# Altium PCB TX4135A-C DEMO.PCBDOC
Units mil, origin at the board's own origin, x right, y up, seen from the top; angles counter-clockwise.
Board outline 1900 x 1181.1 mil, 2 copper layers (Top Layer, Bottom Layer); 15 components, 16 nets, 45 pads, 125 vias.
Unrouted connection lines stored in the file: 6.
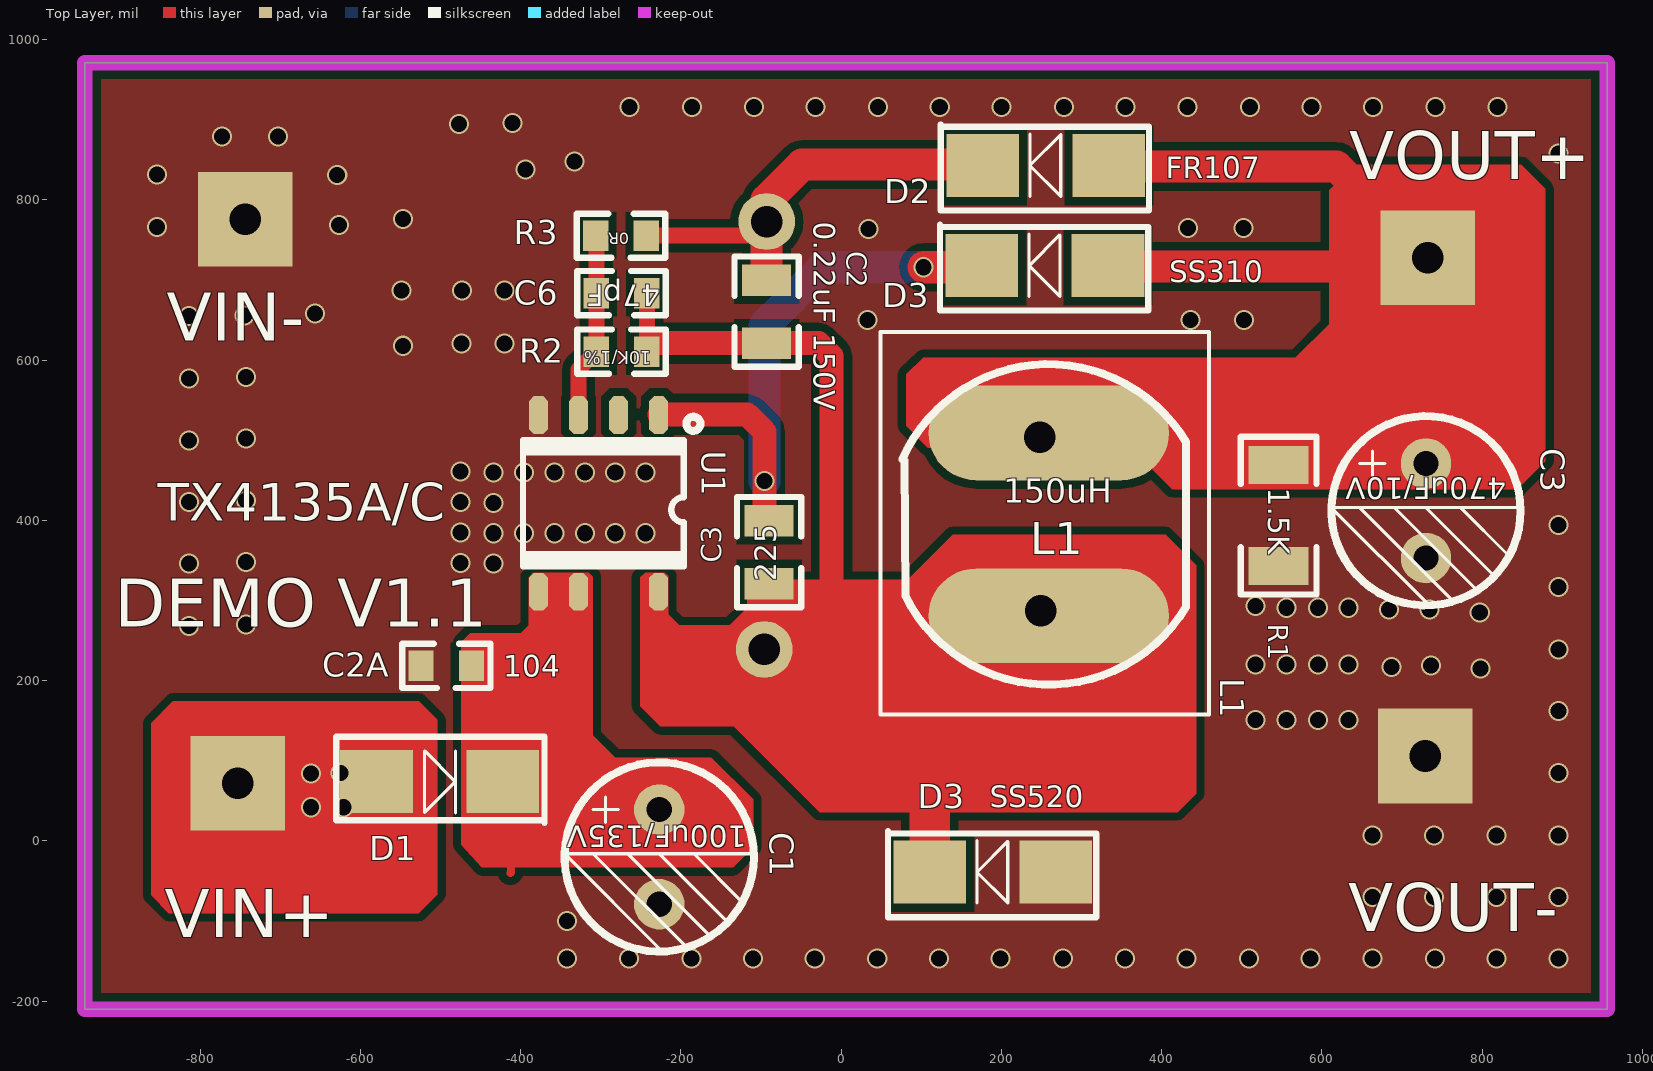
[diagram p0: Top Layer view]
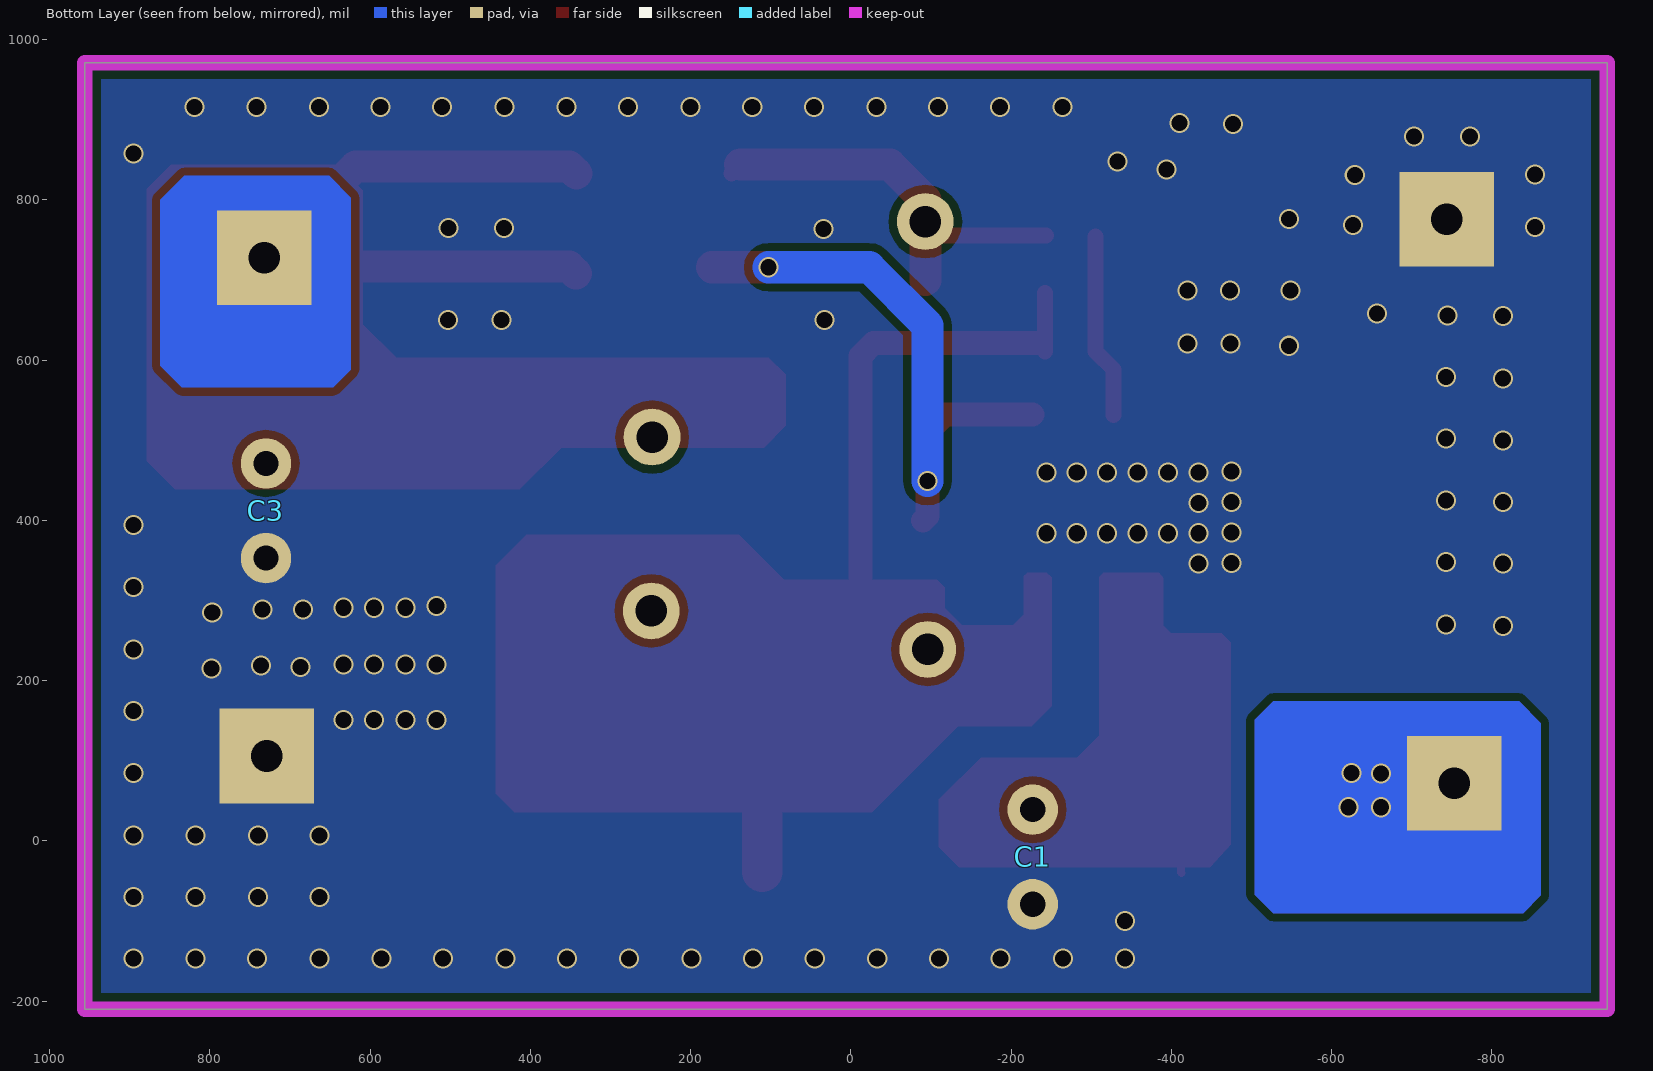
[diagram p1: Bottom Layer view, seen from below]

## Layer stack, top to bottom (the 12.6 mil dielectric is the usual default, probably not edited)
Top Layer: signal copper 1.4
Dielectric: dielectric 12.6, FR-4, Dk 4.8
Bottom Layer: signal copper 1.4

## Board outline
-944,-210 956,-210 956,971.1 -944,971.1

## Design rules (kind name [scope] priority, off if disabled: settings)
Clearance [All] p1: gap=10
PlaneConnect [All] p1: planeconnectstyle=NoConnect reliefexpansion=20 reliefentries=4 reliefconductorwidth=10 reliefairgap=10
PolygonConnect [All] p1: connectstyle=Direct reliefconductorwidth=0 reliefentries=4 polygonreliefangle="90 Angle"
RoutingVias [All] p1: holewidth=28 width=50 viastyle="Through Hole" minholewidth=28 minwidth=50 maxholewidth=28 maxwidth=50
SilkscreenOverComponentPads SilkToSolderMaskClearance [IsPad] p1: minsilkscreentomaskgap=10
SolderMaskExpansion [All] p1: expansion=4
TestPointUsage [All] p1: valid=0 allowmultiple=FALSE
Testpoint [All] p1: side=3 testpointundercomponent=TRUE minsize=40 maxsize=100 preferedsize=60 minholesize=0 maxholesize=40 preferedholesize=32 testpointgrid=1 style=297 order=0123456789
Width [All] p1: maxlimit=100 minlimit=10 preferedwidth=10
22 further rules are at their usual default settings.

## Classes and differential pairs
component class 6321&8321&6322&8322: R6

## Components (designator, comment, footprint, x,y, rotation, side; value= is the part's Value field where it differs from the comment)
C1 "100uF/135V" C6 -239,-7 r270 bottom
C2 "0.22uF 150V" 0805 -93,700 r270 top (schematic designator C5)
C2A "104" 0603 -488,213 r180 top (schematic designator C2)
C3 "225" 0805 -90,321 r90 top (schematic designator C5)
C3 "470uF/10V" C6 718,425 r270 bottom
C6 "47pF" 0603 -279,689 r0 top
D1 "" SMA -580,74 r0 top (schematic designator C4)
D2 "FR107" SMA 334,843 r180 top (schematic designator C4)
D3 "SS520" SMA 268,-39 r180 top (schematic designator C4)
D3 "SS310" SMA 333,718 r180 top (schematic designator C4)
L1 "" CD105 259,395 r180 top
R1 "1.5K" 1206 546,469 r270 top (schematic designator C5)
R2 "10K/1%" 0603 -279,616 r0 top
R3 "0R" 0603 -270,750 r180 top (schematic designator R1)
U1 "TX4135A/C" ESOP-8A -293,429 r270 top

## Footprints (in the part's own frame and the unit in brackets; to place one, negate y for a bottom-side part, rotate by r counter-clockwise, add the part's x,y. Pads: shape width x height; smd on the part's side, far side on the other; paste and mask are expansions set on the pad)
0603 [mm]
  rect 0.8x0.965 smd: 1(0.923,-0.136) 2(-0.677,-0.136)
  silkscreen extent -1.28,-0.84 1.52,0.56
0805 [mm]
  rect 1x1.55 smd: 1(0,0) 2(2,0)
  silkscreen extent -0.75,-1.02 2.75,1.02
1206 [mm]
  rect 1.2x1.9 smd: 1(0,0) 2(3.2,0)
  silkscreen extent -0.9,-1.2 4.1,1.2
C6 [mm]
  round 1.6 hole 0.8: 1(-1.17,-0.303) 2(1.83,-0.303)
CD105 [mm]
  oval 7.62x3 smd: 1(0,-2.9) 2(0,2.9)
  silkscreen extent -4.36,-5.08 4.64,5.08
ESOP-8A [mm]
  oct 1.2x0.6 smd: 1(-2.603,1.654) 2(-2.603,0.384) 3(-2.603,-0.886) 4(-2.603,-2.156) 5(2.997,-2.156) 6(2.997,-0.886) 8(2.997,1.654)
  oct 0x0 smd: 7(2.997,0.384)
  rect 0x0 smd: ""(0.2,-0.1)
  silkscreen extent -2.55,-2.65 2.2,2.98
SMA [mm]
  rect 2.3x2 smd: 1(0,0) 2(4,0)
  silkscreen extent -1.28,-1.3 5.33,1.43

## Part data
C1 C3: library part "Cap Pol3", "Polarized Capacitor (Surface Mount)"
C2 C2A C3 C6 D1 D2 D3 D3 R1: library part "Cap Semi", "Capacitor (Semiconductor SIM Model)"
L1: library part INDUCTOR
R2 R3: library part "Res Semi", "Semiconductor Resistor"
U1: library part PL6321

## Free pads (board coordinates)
  rect 118.11x118.11 hole 39.37: 0(-753,72) 0(-744,776) 0(729,106) 0(732,728)
  round 70.87 hole 39.37: 0(248,504) 1(-96,239) 1(-93,773) 1(249,287)

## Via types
v1: diameter 25, hole 20, Top Layer to Bottom Layer, 125 vias

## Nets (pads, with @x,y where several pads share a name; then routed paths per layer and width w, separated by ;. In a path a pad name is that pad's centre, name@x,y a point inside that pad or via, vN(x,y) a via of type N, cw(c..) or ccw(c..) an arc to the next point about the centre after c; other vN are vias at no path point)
12V: D1.1 pad.0@-753,72
  other v1: -662,42 -621,42 -662,84 -625,85
EN: U1.7
GND: C1.2 C2A.1 C3.2@729.93,352.95 D3.1@268,-39 pad.0@729,106 pad.0@-744,776 R1.2 U1. U1.4
  other v1: -342,-147 -265,-147 -187,-147 -110,-147 -33,-147 45,-147 122,-147 199,-147 277,-147 354,-147 431,-147 509,-147 586,-147 663,-147 741,-147 818,-147 895,-147 -342,-100 663,-70 740,-70 818,-70 895,-70 663,7 740,7 818,7 895,7 895,85 517,151 556,151 595,151 633,151 895,162 798,215 687,217 736,219 517,220 556,220 595,220 633,220 895,239 -814,268 -743,270 797,285 684,289 734,289 556,291 595,291 633,291 517,293 895,317 -814,346 -434,346 -475,347 -743,348 -434,384 -396,384 -358,384 -320,384 -282,384 -244,384 -475,385 895,394 -434,422 -814,423 -475,423 -743,425 -434,460 -396,460 -358,460 -320,460 -282,460 -244,460 -475,461 -814,500 -743,502 -814,577 -743,579 -547,618 -474,621 -420,621 33,650 436,650 503,650 -814,655 -745,656 -657,658 -549,687 -473,687 -420,687 34,764 433,765 502,765 -854,766 -627,769 -547,776 -629,831 -854,832 -394,838 -333,848 895,858 -773,879 -703,879 -477,895 -410,896 -264,916 -186,916 -109,916 -32,916 46,916 123,916 200,916 278,916 355,916 432,916 510,916 587,916 664,916 742,916 819,916
NetC1_1: C1.1 C2A.2 D1.2 U1.2 | length 379.4
  Top Layer w10: -413.01,-40 -412.35,-39.35 D1.2@-412.35,63.35
  Top Layer w35: D1.2@-402.81,64.8 -402.81,74 -402.81,191.19 -328,266 -328,309.64
NetC3_1: C3.1@729.93,471.06 D2.1 D3.1@333,718 L1.1 pad.0@248,504 pad.0@732,728 R1.1 | length 755.9
  Top Layer w40: D2.1@342.45,833 343.22,833.78 351.45,842 618,842 pad.0@732,728 ; D3.1@343,708 352,717 649,717 653,713
NetC5_1: C3.1@-90,321
NetC5_2: C2.2 C6.1 D3.2@110.52,-39 L1.2 pad.1@249,287 pad.1@-96,239 R2.1 U1.8 | length 850.2
  Top Layer w20: R2.1 C6.1 ; pad.1@-63,242 -31,242 -12,261
  Top Layer w30: R2.1@-232.05,621.26 C2.2 -28.26,621.26 -12,605 -12,261
  Top Layer w50: D3.2@110.52,-39 110.52,108.52
NetC6_2: C6.2 R2.2 R3.1 U1.3 | length 232.4
  Top Layer w20: U1.3 -327.88,588.42 R2.2 C6.2 R3.1@-305.65,754.67
NetC7_2: 
NetLED_1: 
NetR3_2: 
NetR5_1: C3.2@-90,399.74 D3.2@175.52,718 U1.1 | length 748.4
  Top Layer w20: U1.1 U1.1@-227.02,532.34
  Top Layer w30: U1.1@-227.02,532.34 -117.34,532.34 -95.65,510.65 v1(-95.65,449) -95.65,405.39 C3.2@-90,399.74
  Top Layer w40: v1(103,716) D3.2@173.52,716
  Bottom Layer w40: v1(-95.65,449) -95.65,643.35 -23,716 v1(103,716)
NetR6_1: C2.1 D2.2 pad.1@-93,773 R3.2 | length 510.4
  Top Layer w20: R3.2 pad.1@-97.35,755.35 ; D2.2@137.97,844 D2.2@148.74,833.22
  Top Layer w40: C2.1 -93,773 -93,800 -49,844 D2.2@137.97,844
NetR7_2: 
U1-6: U1.5 U1.6
USB-6: 

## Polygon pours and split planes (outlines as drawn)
GND on Top Layer "TopLayer-No Net" (solid, remove dead copper, pour order 1000): -944,971.1 -940,967.1 958,967.1 958,-210.9 954,-214.9 948,-220.9 -942,-220.9
GND on Bottom Layer "TopLayer-No Net" (solid, remove dead copper, pour order 1001): -944,971.1 -940,967.1 958,967.1 958,-210.9 954,-214.9 948,-220.9 -942,-220.9

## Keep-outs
Keep-Out Layer:
  the board outline again, w19.68

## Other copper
Top Layer:
  region: -385,335 -315,335 -310,330 -310,132 -282,104 -162,104 -110,52 -110,-8 -135,-33 -448.48,-33 -474,-4.75 -474,248 -463,259 -400,259 -390.09,268.91 -389.72,328.24
  region net 12V: -834,174 -527,174 -504,151 -504,-67 -527,-90 -839,-90 -861,-68 -861,147
  region net NetC3_1: 102.38,603 567,603 609,645 609,812 641,844 849,844 879,814 879,474 844,439 413,439 361,491 108,491 81,518 81,582.41
  region net NetC5_2: -244.58,335 -220,335 -216,331 -216,283 -202,269 -139,269 -117.2,290.8 -117.2,316.8 -108,326 83,326 139,382 405,382 443,344 443,59 420,36 -27,36 -134,143 -226,143 -251,168 -251,329.37
Bottom Layer:
  region net 12V: 651,830 832,830 862,800 862,593 835,566 646,566 624,588 624,803
  region net 12V: -834,174 -527,174 -504,151 -504,-67 -527,-90 -839,-90 -861,-68 -861,147

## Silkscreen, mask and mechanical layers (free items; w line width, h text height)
Top Overlay:
  lines w5: 49,158 49,635 459,635 459,158 49,158
  text "VOUT+" at 634.36,825.64 h60
  text "VIN-" at -842,624 h60
  text "150uH" at 202,422 h30
  text "DEMO V1.1" at -907,267 h60
  text "L1" at 473,203 h30 r270
  text "VOUT-" at 633,-113 h60
  text "VIN+" at -844,-120 h60
Bottom Solder:
  region: -386,474 -386,368 -222,368 -222,474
